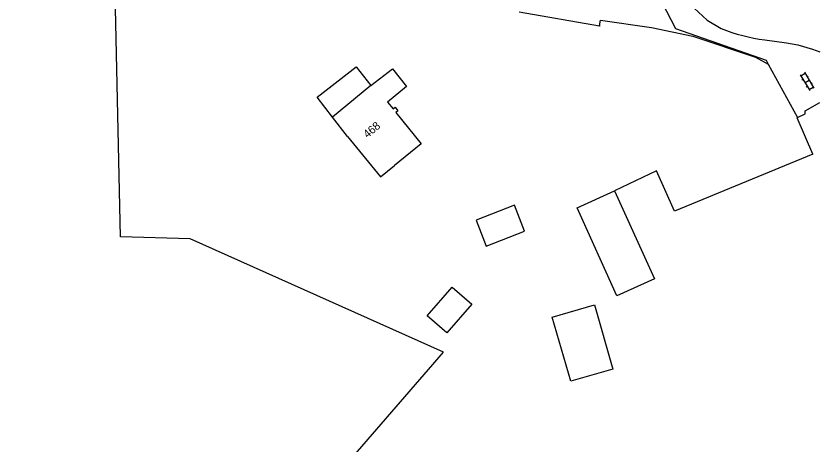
# Model space of a CAD drawing. Extents: x 128999 to 131010, y 395498 to 399007.
# Drawn here: x 130899.6 to 131000, y 396536 to 396589.5 of the extents above; entities that cross this region are included whole.
import ezdxf

# ---------------------------------------------------------------- set-up
doc = ezdxf.new("R2010")
doc.units = 0
for name, color, linetype in [('gg-afsc-erfafscheiding', 7, 'Continuous'), ('gg-afsc-hekwerk', 7, 'Continuous'), ('gg-anno-huisnummerreeks BGT', 7, 'Continuous'), ('gg-bbg-gedigitaliseerde bebouwing', 7, 'Continuous'), ('gg-bbg-gedigitaliseerde bijgebouw', 7, 'Continuous'), ('gg-bbg-hoofdgebouw', 7, 'Continuous'), ('gg-bbg-luifel en loopbrug', 7, 'Continuous'), ('gg-bbg-overig bouwwerk', 7, 'Continuous'), ('gg-knt-verharding', 7, 'Continuous'), ('gt-grn-vlakafsluiter', 7, 'Continuous'), ('gt-symb-klinker verharding', 7, 'Continuous')]:
    doc.layers.add(name, color=color, linetype=linetype)

# ---------------------------------------------------------------- blocks, each defined once
blk = doc.blocks.new('gt0-KL1')
at = {"layer": 'gt-symb-klinker verharding'}
for p, q in [((-1.15, 0.3), (1.15, 0.3)), ((-1, -0.3), (-1, 0.3)), ((-0.5, 0.3), (-0.5, 0.45)), ((0, -0.3), (0, 0.3)), ((0.5, 0.3), (0.5, 0.45)), ((1, -0.3), (1, 0.3)), ((-1.15, -0.3), (1.15, -0.3)), ((-0.5, -0.45), (-0.5, -0.3)), ((0.5, -0.45), (0.5, -0.3))]:
    blk.add_line(p, q, dxfattribs=at)

msp = doc.modelspace()

# ---------------------------------------------------------------- linework, layer by layer
at = {"layer": 'gg-afsc-erfafscheiding'}
for points in [[(130972.48, 396588.3), (130972.58, 396588.98), (130978.96, 396588.08), (130984.13, 396586.98), (130991.94, 396584.37), (130993.54, 396583.52)], [(130999.11, 396572.26), (130981.85, 396565.18), (130979.58, 396570.19), (130974.34, 396567.68)]]:
    msp.add_lwpolyline(points, dxfattribs=at)
at = {"layer": 'gg-afsc-hekwerk'}
for p, q in [((130962.42, 396590.02), (130972.48, 396588.3)), ((130972.48, 396588.3), (130972.57, 396588.28)), ((130997.15, 396576.8), (130997.22, 396576.84)), ((130999.11, 396572.26), (130997.15, 396576.8))]:
    msp.add_line(p, q, dxfattribs=at)
msp.add_lwpolyline([(130997.22, 396576.84), (130998.15, 396577.32), (130998.15, 396577.69), (131000, 396578.71)], dxfattribs=at)
at = {"layer": 'gg-bbg-gedigitaliseerde bebouwing'}
for p, q in [((130943.92, 396580.82), (130946.62, 396582.92)), ((130943.92, 396580.82), (130939.12, 396576.9)), ((130940.99, 396574.49), (130939.12, 396576.9)), ((130950.21, 396573.58), (130946.85, 396570.85))]:
    msp.add_line(p, q, dxfattribs=at)
msp.add_lwpolyline([(130940.99, 396574.49), (130945.12, 396569.44), (130946.85, 396570.85)], dxfattribs=at)
at = {"layer": 'gg-bbg-gedigitaliseerde bijgebouw'}
for points in [[(130950.95, 396552.1), (130954.06, 396555.69), (130956.52, 396553.56), (130953.4, 396549.97), (130950.95, 396552.1)], [(130966.56, 396551.96), (130971.83, 396553.48), (130974.14, 396545.46), (130968.88, 396543.94), (130966.56, 396551.96)]]:
    msp.add_lwpolyline(points, dxfattribs=at)
at = {"layer": 'gg-bbg-hoofdgebouw'}
msp.add_lwpolyline([(130946.62, 396582.92), (130948.36, 396580.73), (130945.99, 396578.76), (130946.69, 396577.91), (130946.95, 396578.12), (130947.3, 396577.7), (130947.03, 396577.48), (130950.21, 396573.58)], dxfattribs=at)
at = {"layer": 'gg-bbg-luifel en loopbrug'}
for points in [[(130939.12, 396576.9), (130937.19, 396579.38), (130942.07, 396583.18), (130943.92, 396580.82)], [(130957.05, 396564.05), (130958.3, 396560.81), (130963.11, 396562.67), (130961.86, 396565.91), (130957.05, 396564.05)]]:
    msp.add_lwpolyline(points, dxfattribs=at)
at = {"layer": 'gg-bbg-overig bouwwerk'}
msp.add_lwpolyline([(130974.34, 396567.68), (130979.32, 396556.73), (130974.65, 396554.61), (130969.67, 396565.56), (130974.34, 396567.68)], dxfattribs=at)
at = {"layer": 'gg-knt-verharding'}
msp.add_line((130993.54, 396583.52), (130997.22, 396576.84), dxfattribs=at)
for points in [[(130979.12, 396593.42), (130981.97, 396587.93), (130993.27, 396584), (130993.54, 396583.52)], [(130981.41, 396593.5), (130983.77, 396590.97), (130985.91, 396588.98), (130987.68, 396587.93)], [(130993.12, 396586.52), (130995.82, 396586.17), (130997.26, 396585.9), (130999.07, 396585.37), (131000, 396585.03)]]:
    msp.add_lwpolyline(points, dxfattribs=at)
msp.add_arc((130996.31, 396610.06), 23.75, 248.6889, 262.2795, dxfattribs=at)
at = {"layer": 'gt-grn-vlakafsluiter'}
msp.add_lwpolyline([(130947.81, 396341.12), (130899.6, 396470.1), (130930.95, 396522.18), (130953, 396547.58), (130921.35, 396561.7), (130912.65, 396561.98), (130911.91, 396596.23)], dxfattribs=at)

# ---------------------------------------------------------------- block references
at = {"layer": 'gt-symb-klinker verharding', "rotation": -58.869200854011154}
msp.add_blockref('gt0-KL1', (130998.4, 396581.35), dxfattribs=at)

# ---------------------------------------------------------------- texts
at = {"layer": 'gg-anno-huisnummerreeks BGT'}
msp.add_text('468', height=1, rotation=39.8, dxfattribs=at).set_placement((130943.48, 396574.22))

doc.saveas('drawing.dxf')
